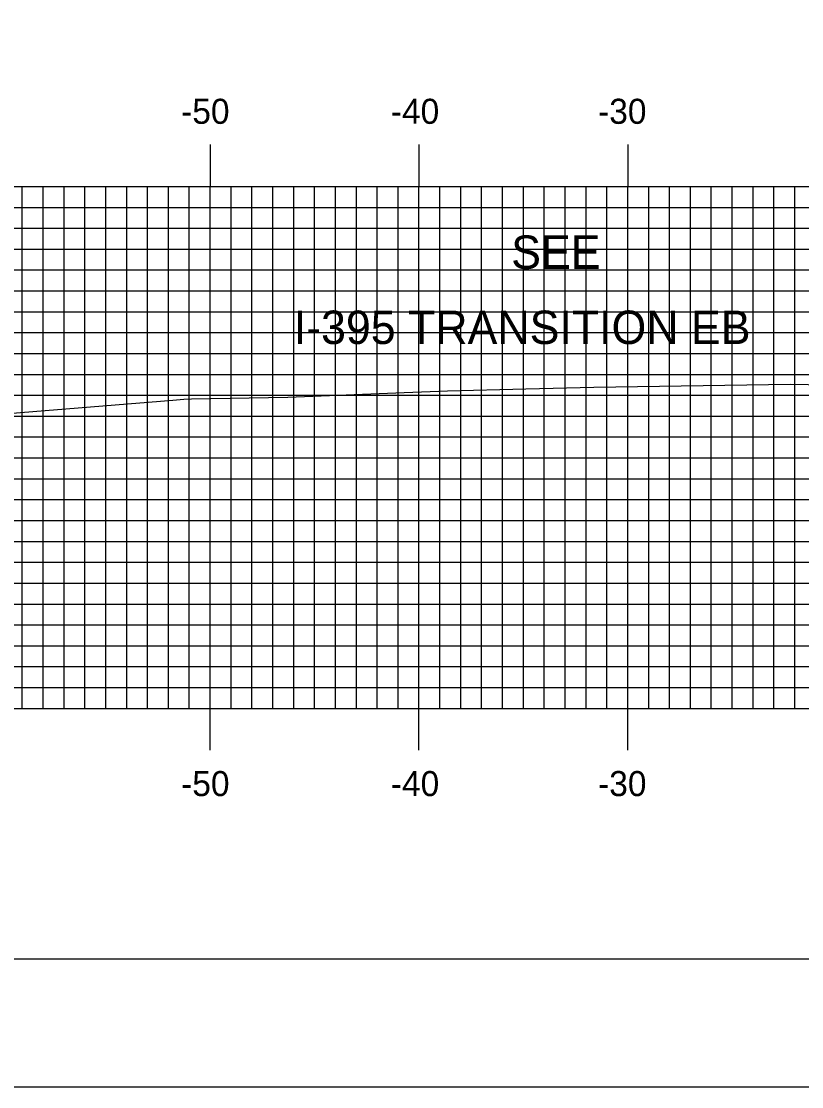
# Model space of a CAD drawing. Extents: x 844536 to 844879, y 363538 to 363758.
# Drawn here: x 844642.9 to 844680.3, y 363537.6 to 363588.6 of the extents above; entities that cross this region are included whole.
import ezdxf

# ---------------------------------------------------------------- set-up
doc = ezdxf.new("R2010")
doc.units = 0
for name, color, linetype in [('ANNOTATION', 7, 'Continuous'), ('BORDER', 7, 'Continuous'), ('H_V ANNOTATION', 7, 'Continuous'), ('MAJOR', 7, 'Continuous'), ('MINOR', 7, 'Continuous'), ('PLOT BOUNDARY', 7, 'Continuous'), ('S_Roadway_Centerline', 7, 'Continuous')]:
    doc.layers.add(name, color=color, linetype=linetype)

msp = doc.modelspace()

# ---------------------------------------------------------------- linework, layer by layer
at = {"layer": 'BORDER'}
msp.add_lwpolyline([(844552.364, 363543.721), (844872.364, 363543.721), (844872.364, 363753.721), (844552.364, 363753.721)], close=True, dxfattribs=at)
at = {"layer": 'MAJOR'}
for p, q in [((844651.964, 363582.725), (844651.964, 363580.721)), ((844661.964, 363582.725), (844661.964, 363580.721)), ((844671.964, 363582.725), (844671.964, 363580.721)), ((844561.964, 363580.721), (844841.964, 363580.721)), ((844561.964, 363580.721), (844841.964, 363580.721)), ((844651.964, 363555.721), (844651.964, 363580.721)), ((844661.964, 363555.721), (844661.964, 363580.721)), ((844671.964, 363555.721), (844671.964, 363580.721)), ((844561.964, 363575.721), (844841.964, 363575.721)), ((844561.964, 363570.721), (844841.964, 363570.721)), ((844561.964, 363565.721), (844841.964, 363565.721)), ((844561.964, 363560.721), (844841.964, 363560.721)), ((844561.964, 363555.721), (844841.964, 363555.721)), ((844561.964, 363555.721), (844841.964, 363555.721)), ((844651.964, 363553.717), (844651.964, 363555.721)), ((844661.964, 363553.717), (844661.964, 363555.721)), ((844671.964, 363553.717), (844671.964, 363555.721))]:
    msp.add_line(p, q, dxfattribs=at)
at = {"layer": 'MINOR'}
for p, q in [((844642.964, 363555.721), (844642.964, 363580.721)), ((844643.964, 363555.721), (844643.964, 363580.721)), ((844644.964, 363555.721), (844644.964, 363580.721)), ((844645.964, 363555.721), (844645.964, 363580.721)), ((844646.964, 363555.721), (844646.964, 363580.721)), ((844647.964, 363555.721), (844647.964, 363580.721)), ((844648.964, 363555.721), (844648.964, 363580.721)), ((844649.964, 363555.721), (844649.964, 363580.721)), ((844650.964, 363555.721), (844650.964, 363580.721)), ((844652.964, 363555.721), (844652.964, 363580.721)), ((844653.964, 363555.721), (844653.964, 363580.721)), ((844654.964, 363555.721), (844654.964, 363580.721)), ((844655.964, 363555.721), (844655.964, 363580.721)), ((844656.964, 363555.721), (844656.964, 363580.721)), ((844657.964, 363555.721), (844657.964, 363580.721)), ((844658.964, 363555.721), (844658.964, 363580.721)), ((844659.964, 363555.721), (844659.964, 363580.721)), ((844660.964, 363555.721), (844660.964, 363580.721)), ((844662.964, 363555.721), (844662.964, 363580.721)), ((844663.964, 363555.721), (844663.964, 363580.721)), ((844664.964, 363555.721), (844664.964, 363580.721)), ((844665.964, 363555.721), (844665.964, 363580.721)), ((844666.964, 363555.721), (844666.964, 363580.721)), ((844667.964, 363555.721), (844667.964, 363580.721)), ((844668.964, 363555.721), (844668.964, 363580.721)), ((844669.964, 363555.721), (844669.964, 363580.721)), ((844670.964, 363555.721), (844670.964, 363580.721)), ((844672.964, 363555.721), (844672.964, 363580.721)), ((844673.964, 363555.721), (844673.964, 363580.721)), ((844674.964, 363555.721), (844674.964, 363580.721)), ((844675.964, 363555.721), (844675.964, 363580.721)), ((844676.964, 363555.721), (844676.964, 363580.721)), ((844677.964, 363555.721), (844677.964, 363580.721)), ((844678.964, 363555.721), (844678.964, 363580.721)), ((844679.964, 363555.721), (844679.964, 363580.721)), ((844561.964, 363579.721), (844841.964, 363579.721)), ((844561.964, 363578.721), (844841.964, 363578.721)), ((844561.964, 363577.721), (844841.964, 363577.721)), ((844561.964, 363576.721), (844841.964, 363576.721)), ((844561.964, 363574.721), (844841.964, 363574.721)), ((844561.964, 363573.721), (844841.964, 363573.721)), ((844561.964, 363572.721), (844841.964, 363572.721)), ((844561.964, 363571.721), (844841.964, 363571.721)), ((844561.964, 363569.721), (844841.964, 363569.721)), ((844561.964, 363568.721), (844841.964, 363568.721)), ((844561.964, 363567.721), (844841.964, 363567.721)), ((844561.964, 363566.721), (844841.964, 363566.721)), ((844561.964, 363564.721), (844841.964, 363564.721)), ((844561.964, 363563.721), (844841.964, 363563.721)), ((844561.964, 363562.721), (844841.964, 363562.721)), ((844561.964, 363561.721), (844841.964, 363561.721)), ((844561.964, 363559.721), (844841.964, 363559.721)), ((844561.964, 363558.721), (844841.964, 363558.721)), ((844561.964, 363557.721), (844841.964, 363557.721)), ((844561.964, 363556.721), (844841.964, 363556.721))]:
    msp.add_line(p, q, dxfattribs=at)
at = {"layer": 'PLOT BOUNDARY'}
msp.add_lwpolyline([(844536.177, 363537.603), (844876.177, 363537.603), (844876.177, 363757.603), (844536.177, 363757.603)], close=True, dxfattribs=at)
at = {"layer": 'S_Roadway_Centerline'}
msp.add_lwpolyline([(844631.035, 363568.935), (844650.171, 363570.478), (844650.7, 363570.53), (844651.069, 363570.542), (844655.683, 363570.623), (844661.254, 363570.845), (844663.322, 363570.939), (844667.073, 363571.022), (844670.333, 363571.106), (844679.76, 363571.247), (844689.824, 363571.067)], dxfattribs=at)

# ---------------------------------------------------------------- texts
at = {"layer": 'ANNOTATION'}
for s, p in [('SEE', (844666.38, 363576.774)), ('I-395 TRANSITION EB', (844655.967, 363573.174))]:
    msp.add_text(s, height=1.6, dxfattribs=at).set_placement(p)
at = {"layer": 'H_V ANNOTATION'}
for s, p in [('-50', (844650.572, 363583.721)), ('-40', (844660.615, 363583.721)), ('-30', (844670.54, 363583.721)), ('-50', (844650.572, 363551.521)), ('-40', (844660.615, 363551.521)), ('-30', (844670.54, 363551.521))]:
    msp.add_text(s, height=1.2, dxfattribs=at).set_placement(p)

doc.saveas('drawing.dxf')
